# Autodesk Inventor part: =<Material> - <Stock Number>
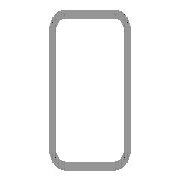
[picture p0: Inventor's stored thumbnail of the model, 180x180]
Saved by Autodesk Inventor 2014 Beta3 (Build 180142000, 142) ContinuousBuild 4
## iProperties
IsCustomPart: 1
Created: 2013-01
Part Number: =<Material> - <Stock Number>
Material: Steel, Mild
Description: Tube
Document SubType Name: Modeling
Standard: ANSI
Designer: Thomas
Standards Organization: ANSI
Language: en-US
Size Designation: 5x3x3/16
Categories: <MemberInstance><Categories><Category DisplayName="Structural Shapes" InternalName="089c4875-fa83-4c05-b084-43b9cc11f5ed" Mnemonic="GRDR"><CategoryParameter Dis
Stock Number: 5x3x3/16
Density: 7.86 g/cm^3
Appearance: Steel
_CCFamilyMember: 33
_CCFamilyDisplayName: ANSI AISC (Rectangular) - Tube
_FrameMemberDoc: Frame Member File
_Version: 15.0.0
_GetPNFromCC: 1
G_L: 18.747 in
G_W: 3.000 in
G_H: 5.000 in
+81598EE7-2C8A-4684-9D57-2FF5DF881D44+CUTDETAIL1: Cut
+9951DD3C-6153-424A-A551-3E22ECA78F0B+CUTDETAIL2: Cut
Author: Thomas
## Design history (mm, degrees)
node "Start plane"
node "End plane"
node "Driven Length"
  sketch "Sketch3"
    geometry: L1 (0, 0)-(10, 0) reference
    constraints: 2 end point, 1 horizontal
  workplane "Work Plane3"
  sketch "Sketch4"
    geometry: L1 (-2, 0)-(12, 0) reference; L2 (-53.343, 476.185)-(53.343, 476.185) reference
    dimensions: "d19" = 476.18539 distance between parallel lines of L1 L2 (derived)
sketch "Sweep Path"
  geometry: L1 through (609.6, 0) direction (1, 0); 1 other entity
  constraints: 5 horizontal
node "Orientation Work Plane"
feature "Body" dims "d20" = 0
workplane "Work Plane5"
sketch "Sketch5"
  geometry: L1 (-38.6, 73.96)-(38.6, 73.96); L2 (-38.6, -73.96)-(38.6, -73.96)
  constraints: 4 end point
feature "LoftSrf1" sketch "Sketch5" dims "d21" = 0, "d22" = 90 deg, "d23" = 0, "d24" = 90 deg
split "Split1"
workplane "Work Plane6"
sketch "Sketch6"
  geometry: L1 (-38.6, 73.96)-(38.6, 73.96); L2 (-38.6, -73.96)-(38.6, -73.96)
  constraints: 4 end point
feature "LoftSrf2" sketch "Sketch6" dims "d25" = 0, "d26" = 90 deg, "d27" = 0, "d28" = 90 deg
split "Split2"
body "Solid1"
sketch "Sketch"
  geometry: L1 (-38.1, -53.975)-(-38.1, 53.975); L2 (-28.575, 63.5)-(28.575, 63.5); L3 (38.1, 53.975)-(38.1, -53.975); L4 (28.575, -63.5)-(-28.575, -63.5); L5 (-28.575, 58.737)-(28.575, 58.737); L6 (33.338, 53.975)-(33.338, -53.975); L7 (28.575, -58.737)-(-28.575, -58.737); L8 (-33.338, -53.975)-(-33.338, 53.975); L9 (0, 36.948)-(0, -36.948); L10 (-23.079, 0)-(23.079, 0); A1 r 9.525 centre (-28.575, -53.975) between (-38.1, -53.975) and (-28.575, -63.5); A2 r 9.525 centre (-28.575, 53.975) between (-28.575, 63.5) and (-38.1, 53.975); A3 r 9.525 centre (28.575, 53.975) between (38.1, 53.975) and (28.575, 63.5); A4 r 9.525 centre (28.575, -53.975) between (28.575, -63.5) and (38.1, -53.975); A5 r 4.763 centre (-28.575, 53.975) between (-28.575, 58.737) and (-33.338, 53.975); A6 r 4.763 centre (28.575, 53.975) between (33.338, 53.975) and (28.575, 58.737); A7 r 4.763 centre (28.575, -53.975) between (28.575, -58.737) and (33.338, -53.975); A8 r 4.763 centre (-28.575, -53.975) between (-33.338, -53.975) and (-28.575, -58.737)
  constraints: 20 end point, 16 point on circle, 8 centre point, 8 tangent, 4 parallel, 3 equal radius, 2 perpendicular, 7 other
  dimensions: "d10" = 127 distance between parallel lines of L2 L4 (= G_H); "d11" = 76.2 distance between parallel lines of L1 L3 (= G_W); "d12" = 4.7625 distance between parallel lines of L3 L6 (= G_T); "d15" = 63.5 distance between parallel lines of L2 L10 (= 0.5 x d10); "d16" = 38.1 distance between parallel lines of L9 L3 (= 0.5 x d11); "d17" = 9.525 radius of A1 (= G_IR)
body "Srf1"
body "Srf2"
other parameters: "G_W" = 76.2 [user parameter; used in 1 equation term], "G_H" = 127 [user parameter; used in 1 equation term], "G_T" = 4.7625 [user parameter; used in 1 equation term], "G_IR" = 9.525 [user parameter; used in 1 equation term], "G_L" = 476.18539 (= d19) [user parameter], "G_OFFSET_START" = 0 [user parameter; used in 1 equation term], "G_OFFSET_END" = 0 [user parameter; used in 1 equation term], "d13" = 0 (computed from G_OFFSET_START), "d14" = 476.18539 (= G_OFFSET_END + B_L), "B_L" = 476.18539 [user parameter; used in 1 equation term], "d18" = 90 deg
